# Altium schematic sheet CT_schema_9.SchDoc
size 297 x 239 mm
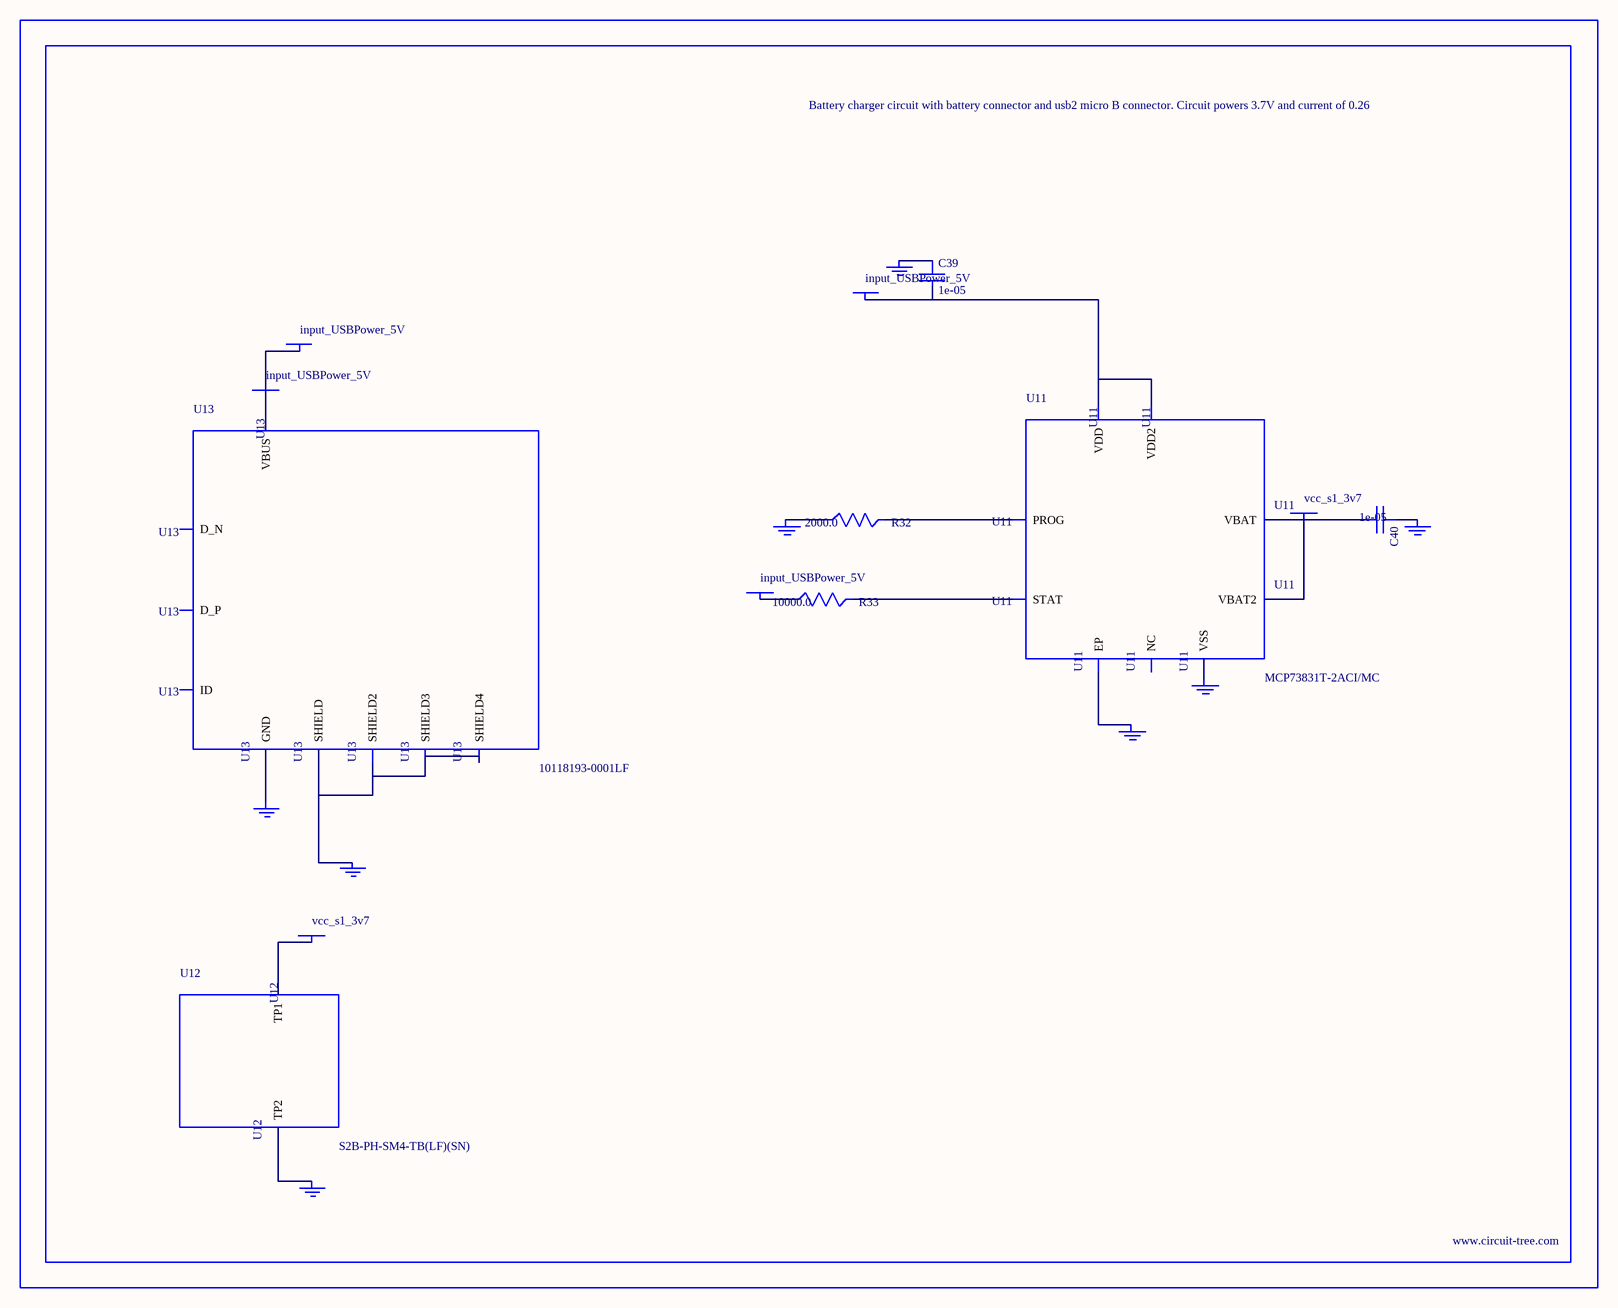
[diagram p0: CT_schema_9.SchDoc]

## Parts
BORDER8  (no value)
C39  1e-05  [C1206]
C40  1e-05  [C1206]
GND_INSTANCE_8_0  (no value)
GND_INSTANCE_8_1  (no value)
GND_INSTANCE_8_2  (no value)
GND_INSTANCE_8_3  (no value)
GND_INSTANCE_8_4  (no value)
GND_INSTANCE_8_5  (no value)
GND_INSTANCE_8_6  (no value)
GND_INSTANCE_8_7  (no value)
POWER_INSTANCE_8_0  input_USBPower_5V
POWER_INSTANCE_8_1  input_USBPower_5V
POWER_INSTANCE_8_2  vcc_s1_3v7
POWER_INSTANCE_8_3  vcc_s1_3v7
POWER_INSTANCE_8_4  input_USBPower_5V
POWER_INSTANCE_8_5  input_USBPower_5V
R32  2000.0  [R0603]
R33  10000.0  [R0603]
U11  MCP73831T-2ACI/MC  [DFN8_2X3MC]
U12  S2B-PH-SM4-TB(LF)(SN)  [JST-2-SMD]
U13  10118193-0001LF  [FCI_10118193-0001LF]

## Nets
NetC39_1: C39.1 GND_INSTANCE_8_0.0(GND)
NetC39_2: C39.2 POWER_INSTANCE_8_0.0(PWR) U11.1(VDD) U11.2(VDD2)
NetC40_1: C40.1 GND_INSTANCE_8_1.0(GND)
NetC40_2: C40.2 POWER_INSTANCE_8_2.0(PWR) U11.3(VBAT) U11.4(VBAT2)
NetGND_INSTANCE_8_2_0: GND_INSTANCE_8_2.0(GND) R32.1
NetGND_INSTANCE_8_3_0: GND_INSTANCE_8_3.0(GND) U11.9(EP)
NetGND_INSTANCE_8_4_0: GND_INSTANCE_8_4.0(GND) U11.6(VSS)
NetGND_INSTANCE_8_5_0: GND_INSTANCE_8_5.0(GND) U12.2(TP2)
NetGND_INSTANCE_8_6_0: GND_INSTANCE_8_6.0(GND) U13.6(SHIELD) U13.7(SHIELD2) U13.8(SHIELD3) U13.9(SHIELD4)
NetGND_INSTANCE_8_7_0: GND_INSTANCE_8_7.0(GND) U13.5(GND)
NetPOWER_INSTANCE_8_1_0: POWER_INSTANCE_8_1.0(PWR) R33.1
NetPOWER_INSTANCE_8_3_0: POWER_INSTANCE_8_3.0(PWR) U12.1(TP1)
NetPOWER_INSTANCE_8_4_0: POWER_INSTANCE_8_4.0(PWR) POWER_INSTANCE_8_5.0(PWR) U13.1(VBUS)
NetR32_2: R32.2 U11.8(PROG)
NetR33_2: R33.2 U11.5(STAT)

Not connected (* = marked no-connect by the designer): U11 7(NC); U13 2(D_N) 3(D_P) 4(ID)

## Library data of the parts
BORDER8 = BORDER_PAGE8
C39 C40 = C1206C106K3RACTU
GND_INSTANCE_8_0-GND_INSTANCE_8_7 = GND
POWER_INSTANCE_8_0-POWER_INSTANCE_8_5 = PWR
R32 = RC0603JR-072KL
R33 = RC0603JR-0710KL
